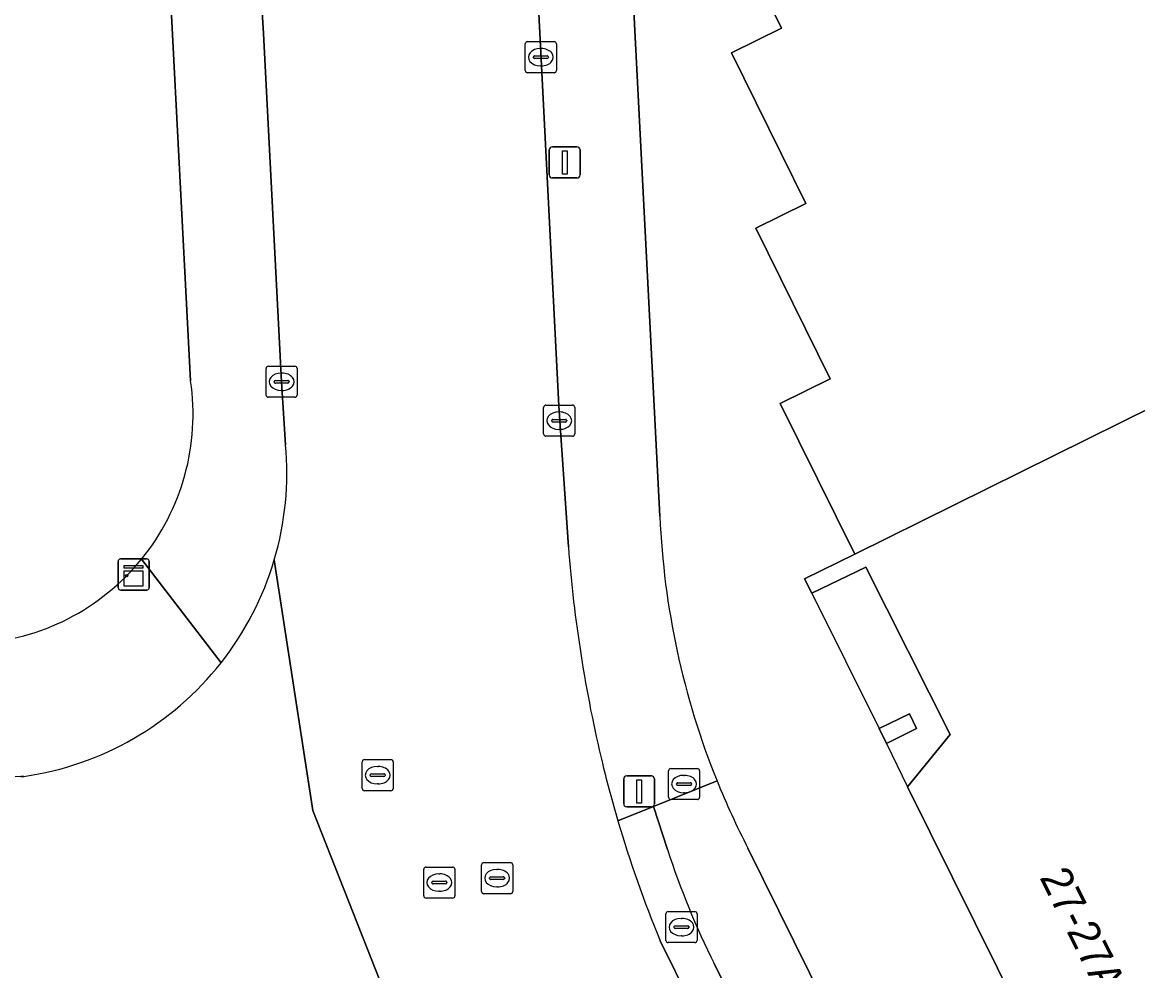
# Model space of a CAD drawing. Extents: x 157692 to 159674, y 381452 to 383291.
# Drawn here: x 158001.47 to 158037.36, y 381590.1 to 381620.62 of the extents above; entities that cross this region are included whole.
import ezdxf

# ---------------------------------------------------------------- set-up
doc = ezdxf.new("R2010")
doc.units = 0
for name, color, linetype in [('IMGEO_Brandkraan', 7, 'Continuous'), ('IMGEO_Erf', 7, 'Continuous'), ('IMGEO_Kast', 7, 'Continuous'), ('IMGEO_Kolk', 7, 'Continuous'), ('IMGEO_Lichtmast', 7, 'Continuous'), ('IMGEO_Pand', 7, 'Continuous'), ('IMGEO_Pand_nummerreeks', 7, 'Continuous'), ('IMGEO_Pand_overbouw', 7, 'Continuous'), ('IMGEO_Rijbaan_lokaal_gesloten', 7, 'Continuous'), ('IMGEO_Rioolput', 7, 'Continuous'), ('IMGEO_Voetpad_open', 7, 'Continuous')]:
    doc.layers.add(name, color=color, linetype=linetype)

msp = doc.modelspace()

# ---------------------------------------------------------------- linework, layer by layer
at = {"layer": 'IMGEO_Brandkraan'}
for p, q in [((158022.261, 381595.679), (158022.261, 381596.531)), ((158022.336, 381596.605), (158023.188, 381596.605)), ((158023.262, 381596.531), (158023.262, 381595.679)), ((158022.52, 381596.099), (158022.52, 381596.111)), ((158022.563, 381596.148), (158022.961, 381596.148)), ((158022.749, 381596.385), (158022.774, 381596.385)), ((158023.004, 381596.111), (158023.004, 381596.099)), ((158022.958, 381596.062), (158022.56, 381596.062)), ((158022.772, 381595.825), (158022.747, 381595.825)), ((158023.188, 381595.605), (158022.336, 381595.605))]:
    msp.add_line(p, q, dxfattribs=at)
for points in [[(158022.261, 381595.679), (158022.261, 381596.531)], [(158022.336, 381596.605), (158023.188, 381596.605)], [(158023.262, 381596.531), (158023.262, 381595.679)], [(158023.188, 381595.605), (158022.336, 381595.605)]]:
    msp.add_lwpolyline(points, dxfattribs=at)
for centre, radius, start, end in [((158022.338, 381596.529), 0.0765, 91.552, 178.448), ((158022.338, 381596.529), 0.0765, 91.552, 178.448), ((158023.186, 381596.529), 0.0765, 1.552, 88.448), ((158023.186, 381596.529), 0.0765, 1.552, 88.448), ((158022.56, 381596.108), 0.0403, 85.8775, 175.7526), ((158022.557, 381596.098), 0.0366, 178.938, 274.7102), ((158022.961, 381596.105), 0.043, 264.8664, 352.4533), ((158022.965, 381596.11), 0.0386, 1.7309, 96.639), ((158022.338, 381595.681), 0.0765, 181.552, 268.448), ((158022.338, 381595.681), 0.0765, 181.552, 268.448), ((158023.186, 381595.681), 0.0765, 271.552, 358.448), ((158023.186, 381595.681), 0.0765, 271.552, 358.448)]:
    msp.add_arc(centre, radius, start, end, dxfattribs=at)
for centre, major_axis, ratio, start_param, end_param in [((158022.748, 381596.105), (-0.387, 0.002), 0.722429, 4.712389, 7.853982), ((158022.773, 381596.105), (-0.39, 0.002), 0.717154, 1.570796, 4.712389)]:
    msp.add_ellipse(centre, major_axis=major_axis, ratio=ratio, start_param=start_param, end_param=end_param, dxfattribs=at)
at = {"layer": 'IMGEO_Erf'}
for points in [[(158006.881, 381609.083), (158005.905, 381627.867), (158005.466, 381636.382), (158005.223, 381641.106), (158032.78, 381654.365), (158038.282, 381657.004), (158060.573, 381667.757), (158067.21, 381670.951), (158069.612, 381672.132), (158075.377, 381674.875), (158095.213, 381684.451), (158107.373, 381690.341), (158121.318, 381697.1), (158122.884, 381701.311), (158109.399, 381729.267), (158106.88, 381734.578), (158102.545, 381743.606), (158102.331, 381744.049), (158099.751, 381749.471), (158099.496, 381750), (158086.302, 381777.417), (158083.311, 381783.632), (158080.659, 381789.142)], [(158024.817, 381594.042), (158031.774, 381579.967), (158034.874, 381573.76), (158035.242, 381573.028), (158037.877, 381567.782), (158119.205, 381608.005), (158123.897, 381610.332), (158120.636, 381617.174), (158120.43, 381617.606), (158147.174, 381630.903), (158223.286, 381668.591), (158222.289, 381671.214), (158214.044, 381692.915)], [(158064.672, 381611.766), (158072.18, 381596.56), (158069.93, 381589.9), (158051.49, 381580.76), (158047.667, 381588.475), (158036.468, 381582.877), (158029.955, 381596.02), (158031.319, 381597.702), (158028.607, 381603.083), (158026.871, 381602.244), (158026.64, 381602.71), (158028.252, 381603.508), (158025.855, 381608.353), (158027.466, 381609.152), (158025.068, 381613.997), (158026.68, 381614.795), (158024.283, 381619.64), (158025.895, 381620.438), (158023.502, 381625.274), (158028.337, 381627.668), (158027.54, 381629.28), (158037.689, 381634.301), (158037.867, 381633.943)], [(158020.806, 381627.665), (158021.984, 381604.726)]]:
    msp.add_lwpolyline(points, dxfattribs=at)
msp.add_lwpolyline([(158030.244, 381597.893), (158029.271, 381597.409), (158029.035, 381597.888), (158030.009, 381598.368)], close=True, dxfattribs=at)
for centre, radius, start, end in [((157999.575, 381608.003), 7.386, 320.8476, 8.406), ((158047.54, 381605.783), 25.578, 182.3676, 201.99), ((157999.568, 381608.009), 7.395, 273.3508, 320.8463), ((158047.696, 381605.866), 25.754, 202.0321, 207.3299)]:
    msp.add_arc(centre, radius, start, end, dxfattribs=at)
at = {"layer": 'IMGEO_Kast'}
for p, q in [((158004.551, 381602.425), (158004.551, 381603.266)), ((158004.551, 381603.266), (158004.551, 381602.425)), ((158004.626, 381603.35), (158005.467, 381603.35)), ((158005.467, 381603.35), (158004.626, 381603.35)), ((158005.551, 381603.275), (158005.551, 381602.434)), ((158005.551, 381602.434), (158005.551, 381603.275)), ((158005.476, 381602.35), (158004.635, 381602.35)), ((158004.635, 381602.35), (158005.476, 381602.35))]:
    msp.add_line(p, q, dxfattribs=at)
for points in [[(158004.746, 381603.14), (158005.346, 381603.14), (158005.346, 381603.055), (158004.746, 381603.055), (158004.746, 381603.14)], [(158004.746, 381602.965), (158005.346, 381602.965), (158005.346, 381602.476), (158004.746, 381602.476), (158004.746, 381602.965)]]:
    msp.add_lwpolyline(points, dxfattribs=at)
msp.add_circle((158004.83, 381602.814), 0.0377, dxfattribs=at)
for centre, start, end in [((158004.629, 381603.272), 92.4484, 184.2845), ((158004.629, 381603.272), 92.4484, 184.2845), ((158005.473, 381603.272), 2.4484, 94.2845), ((158005.473, 381603.272), 2.4484, 94.2845), ((158004.629, 381602.428), 182.4484, 274.2845), ((158004.629, 381602.428), 182.4484, 274.2845), ((158005.473, 381602.428), 272.4484, 4.2845), ((158005.473, 381602.428), 272.4484, 4.2845)]:
    msp.add_arc(centre, 0.0779, start, end, dxfattribs=at)
at = {"layer": 'IMGEO_Kolk'}
for p, q in [((158017.651, 381619.073), (158017.651, 381619.925)), ((158017.726, 381619.999), (158018.578, 381619.999)), ((158018.139, 381619.779), (158018.164, 381619.779)), ((158018.652, 381619.925), (158018.652, 381619.073)), ((158017.91, 381619.493), (158017.91, 381619.505)), ((158018.348, 381619.456), (158017.95, 381619.456)), ((158017.953, 381619.542), (158018.351, 381619.542)), ((158018.394, 381619.505), (158018.394, 381619.493)), ((158018.162, 381619.219), (158018.137, 381619.219)), ((158018.578, 381618.999), (158017.726, 381618.999)), ((158009.31, 381608.626), (158009.31, 381609.478)), ((158009.385, 381609.552), (158010.237, 381609.552)), ((158010.311, 381609.478), (158010.311, 381608.626)), ((158009.569, 381609.046), (158009.569, 381609.058)), ((158010.007, 381609.009), (158009.609, 381609.009)), ((158009.612, 381609.095), (158010.01, 381609.095)), ((158009.798, 381609.332), (158009.823, 381609.332)), ((158010.053, 381609.058), (158010.053, 381609.046)), ((158009.821, 381608.772), (158009.796, 381608.772)), ((158010.237, 381608.552), (158009.385, 381608.552)), ((158018.317, 381608.3), (158019.169, 381608.3)), ((158018.242, 381607.374), (158018.242, 381608.226)), ((158018.73, 381608.08), (158018.755, 381608.08)), ((158019.243, 381608.226), (158019.243, 381607.374)), ((158018.501, 381607.794), (158018.501, 381607.806)), ((158018.939, 381607.757), (158018.541, 381607.757)), ((158018.544, 381607.843), (158018.942, 381607.843)), ((158018.985, 381607.806), (158018.985, 381607.794)), ((158019.169, 381607.3), (158018.317, 381607.3)), ((158018.753, 381607.52), (158018.728, 381607.52)), ((158022.177, 381591.074), (158022.177, 381591.926)), ((158022.252, 381592), (158023.104, 381592)), ((158022.665, 381591.78), (158022.69, 381591.78)), ((158023.178, 381591.926), (158023.178, 381591.074)), ((158022.436, 381591.494), (158022.436, 381591.506)), ((158022.874, 381591.457), (158022.476, 381591.457)), ((158022.479, 381591.543), (158022.877, 381591.543)), ((158022.92, 381591.506), (158022.92, 381591.494)), ((158022.688, 381591.22), (158022.663, 381591.22)), ((158023.104, 381591), (158022.252, 381591))]:
    msp.add_line(p, q, dxfattribs=at)
for points in [[(158017.651, 381619.073), (158017.651, 381619.925)], [(158017.726, 381619.999), (158018.578, 381619.999)], [(158018.652, 381619.925), (158018.652, 381619.073)], [(158018.578, 381618.999), (158017.726, 381618.999)], [(158009.31, 381608.626), (158009.31, 381609.478)], [(158009.385, 381609.552), (158010.237, 381609.552)], [(158010.311, 381609.478), (158010.311, 381608.626)], [(158010.237, 381608.552), (158009.385, 381608.552)], [(158018.317, 381608.3), (158019.169, 381608.3)], [(158018.242, 381607.374), (158018.242, 381608.226)], [(158019.243, 381608.226), (158019.243, 381607.374)], [(158019.169, 381607.3), (158018.317, 381607.3)], [(158022.177, 381591.074), (158022.177, 381591.926)], [(158022.252, 381592), (158023.104, 381592)], [(158023.178, 381591.926), (158023.178, 381591.074)], [(158023.104, 381591), (158022.252, 381591)]]:
    msp.add_lwpolyline(points, dxfattribs=at)
for centre, radius, start, end in [((158017.728, 381619.923), 0.0765, 91.552, 178.448), ((158017.728, 381619.923), 0.0765, 91.552, 178.448), ((158018.576, 381619.923), 0.0765, 1.552, 88.448), ((158018.576, 381619.923), 0.0765, 1.552, 88.448), ((158017.95, 381619.502), 0.0403, 85.8775, 175.7526), ((158017.947, 381619.492), 0.0366, 178.938, 274.7102), ((158018.351, 381619.499), 0.043, 264.8664, 352.4533), ((158018.355, 381619.504), 0.0386, 1.7309, 96.639), ((158017.728, 381619.075), 0.0765, 181.552, 268.448), ((158017.728, 381619.075), 0.0765, 181.552, 268.448), ((158018.576, 381619.075), 0.0765, 271.552, 358.448), ((158018.576, 381619.075), 0.0765, 271.552, 358.448), ((158009.387, 381609.476), 0.0765, 91.552, 178.448), ((158009.387, 381609.476), 0.0765, 91.552, 178.448), ((158010.235, 381609.476), 0.0765, 1.552, 88.448), ((158010.235, 381609.476), 0.0765, 1.552, 88.448), ((158009.609, 381609.055), 0.0403, 85.8775, 175.7526), ((158009.606, 381609.045), 0.0366, 178.938, 274.7102), ((158010.01, 381609.052), 0.043, 264.8664, 352.4533), ((158010.014, 381609.057), 0.0386, 1.7309, 96.639), ((158009.387, 381608.628), 0.0765, 181.552, 268.448), ((158009.387, 381608.628), 0.0765, 181.552, 268.448), ((158010.235, 381608.628), 0.0765, 271.552, 358.448), ((158010.235, 381608.628), 0.0765, 271.552, 358.448), ((158018.319, 381608.224), 0.0765, 91.552, 178.448), ((158018.319, 381608.224), 0.0765, 91.552, 178.448), ((158019.167, 381608.224), 0.0765, 1.552, 88.448), ((158019.167, 381608.224), 0.0765, 1.552, 88.448), ((158018.541, 381607.803), 0.0403, 85.8775, 175.7526), ((158018.538, 381607.793), 0.0366, 178.938, 274.7102), ((158018.942, 381607.8), 0.043, 264.8664, 352.4533), ((158018.946, 381607.805), 0.0386, 1.7309, 96.639), ((158018.319, 381607.376), 0.0765, 181.552, 268.448), ((158018.319, 381607.376), 0.0765, 181.552, 268.448), ((158019.167, 381607.376), 0.0765, 271.552, 358.448), ((158019.167, 381607.376), 0.0765, 271.552, 358.448), ((158022.254, 381591.924), 0.0765, 91.552, 178.448), ((158022.254, 381591.924), 0.0765, 91.552, 178.448), ((158023.102, 381591.924), 0.0765, 1.552, 88.448), ((158023.102, 381591.924), 0.0765, 1.552, 88.448), ((158022.476, 381591.503), 0.0403, 85.8775, 175.7526), ((158022.473, 381591.493), 0.0366, 178.938, 274.7102), ((158022.877, 381591.5), 0.043, 264.8664, 352.4533), ((158022.881, 381591.505), 0.0386, 1.7309, 96.639), ((158022.254, 381591.076), 0.0765, 181.552, 268.448), ((158022.254, 381591.076), 0.0765, 181.552, 268.448), ((158023.102, 381591.076), 0.0765, 271.552, 358.448), ((158023.102, 381591.076), 0.0765, 271.552, 358.448)]:
    msp.add_arc(centre, radius, start, end, dxfattribs=at)
for centre, major_axis, ratio, start_param, end_param in [((158018.138, 381619.499), (-0.387, 0.002), 0.722429, 4.712389, 7.853982), ((158018.163, 381619.499), (-0.39, 0.002), 0.717154, 1.570796, 4.712389), ((158009.797, 381609.052), (-0.387, 0.002), 0.722429, 4.712389, 7.853982), ((158009.822, 381609.052), (-0.39, 0.002), 0.717154, 1.570796, 4.712389), ((158018.729, 381607.8), (-0.387, 0.002), 0.722429, 4.712389, 7.853982), ((158018.754, 381607.8), (-0.39, 0.002), 0.717154, 1.570796, 4.712389), ((158022.664, 381591.5), (-0.387, 0.002), 0.722429, 4.712389, 7.853982), ((158022.689, 381591.5), (-0.39, 0.002), 0.717154, 1.570796, 4.712389)]:
    msp.add_ellipse(centre, major_axis=major_axis, ratio=ratio, start_param=start_param, end_param=end_param, dxfattribs=at)
at = {"layer": 'IMGEO_Lichtmast'}
for p, q in [((158018.525, 381616.613), (158019.315, 381616.613)), ((158019.315, 381616.613), (158018.525, 381616.613)), ((158018.425, 381615.713), (158018.425, 381616.513)), ((158018.425, 381616.513), (158018.425, 381615.713)), ((158019.415, 381616.513), (158019.415, 381615.713)), ((158019.415, 381615.713), (158019.415, 381616.513)), ((158019.315, 381615.613), (158018.525, 381615.613)), ((158018.525, 381615.613), (158019.315, 381615.613)), ((158020.819, 381595.469), (158020.819, 381596.269)), ((158020.819, 381596.269), (158020.819, 381595.469)), ((158020.919, 381596.369), (158021.709, 381596.369)), ((158021.709, 381596.369), (158020.919, 381596.369)), ((158021.809, 381596.269), (158021.809, 381595.469)), ((158021.809, 381595.469), (158021.809, 381596.269)), ((158021.709, 381595.369), (158020.919, 381595.369)), ((158020.919, 381595.369), (158021.709, 381595.369))]:
    msp.add_line(p, q, dxfattribs=at)
for points in [[(158018.845, 381616.488), (158018.995, 381616.488), (158018.995, 381615.738), (158018.845, 381615.738), (158018.845, 381616.488)], [(158021.239, 381596.244), (158021.389, 381596.244), (158021.389, 381595.494), (158021.239, 381595.494), (158021.239, 381596.244)]]:
    msp.add_lwpolyline(points, dxfattribs=at)
for centre, start, end in [((158018.525, 381616.513), 90, 180), ((158018.525, 381616.513), 90, 180), ((158019.315, 381616.513), 0, 90), ((158019.315, 381616.513), 360, 90), ((158018.525, 381615.713), 180, 270), ((158018.525, 381615.713), 180, 270), ((158019.315, 381615.713), 270, 0), ((158019.315, 381615.713), 270, 0), ((158020.919, 381596.269), 90, 180), ((158020.919, 381596.269), 90, 180), ((158021.709, 381596.269), 0, 90), ((158021.709, 381596.269), 360, 90), ((158020.919, 381595.469), 180, 270), ((158020.919, 381595.469), 180, 270), ((158021.709, 381595.469), 270, 0), ((158021.709, 381595.469), 270, 0)]:
    msp.add_arc(centre, 0.1, start, end, dxfattribs=at)
at = {"layer": 'IMGEO_Pand'}
msp.add_lwpolyline([(158037.867, 381633.943), (158037.689, 381634.301), (158027.54, 381629.28), (158028.337, 381627.668), (158023.502, 381625.274), (158025.895, 381620.438), (158024.283, 381619.64), (158026.68, 381614.795), (158025.068, 381613.997), (158027.466, 381609.152), (158025.855, 381608.353), (158028.252, 381603.508), (158037.874, 381608.268), (158041.754, 381600.426), (158064.672, 381611.766), (158053.62, 381634.15), (158047.051, 381630.9)], dxfattribs=at)
for points in [[(158028.252, 381603.508), (158026.64, 381602.71), (158026.871, 381602.244), (158028.607, 381603.083), (158031.319, 381597.702), (158029.955, 381596.02), (158036.468, 381582.877), (158047.667, 381588.475), (158051.49, 381580.76), (158069.93, 381589.9), (158072.18, 381596.56), (158064.672, 381611.766), (158041.754, 381600.426), (158037.874, 381608.268)], [(158029.271, 381597.409), (158030.244, 381597.893), (158030.009, 381598.368), (158029.035, 381597.888)]]:
    msp.add_lwpolyline(points, close=True, dxfattribs=at)
at = {"layer": 'IMGEO_Pand_overbouw'}
msp.add_lwpolyline([(158029.955, 381596.02), (158031.319, 381597.702), (158028.607, 381603.083), (158026.871, 381602.244), (158029.035, 381597.888), (158030.009, 381598.368), (158030.244, 381597.893), (158029.271, 381597.409)], close=True, dxfattribs=at)
at = {"layer": 'IMGEO_Rijbaan_lokaal_gesloten'}
for points in [[(158001.519, 381596.351), (158001.415, 381596.346), (157943.247, 381593.747), (157941.787, 381593.953), (157940.201, 381594.263), (157937.982, 381594.948), (157935.779, 381595.742), (157933.913, 381596.673), (157931.88, 381597.897), (157929.284, 381599.727), (157927.609, 381601.111), (157925.926, 381602.819), (157924.801, 381604.213), (157923.565, 381606.033), (157922.451, 381608.183), (157920.957, 381611.715), (157919.038, 381616.874), (157916.313, 381625.205), (157914.556, 381631.129), (157913.243, 381635.916)], [(158018.776, 381607.631), (158018.733, 381608.273), (158017.739, 381627.652), (158008.979, 381627.772), (158008.948, 381625.733), (158009.154, 381621.489), (158009.233, 381620.257), (158009.812, 381609.052), (158009.936, 381607.028)], [(158019.039, 381603.737), (158018.776, 381607.631)], [(158009.575, 381603.318), (158010.814, 381595.251), (158013.411, 381588.661)], [(158013.411, 381588.661), (158010.814, 381595.251), (158009.575, 381603.318)], [(158017.655, 381585.024), (158019.705, 381580.927), (158025.23, 381569.733), (158025.98, 381568.248), (158031.795, 381571.252), (158031.735, 381571.355), (158030.425, 381574.007), (158021.989, 381591.063)]]:
    msp.add_lwpolyline(points, dxfattribs=at)
for centre, radius, start, end in [((158000.095, 381606.113), 9.884, 343.5729, 5.3118), ((158062.743, 381607.039), 43.828, 184.3208, 193.5424), ((158000.097, 381606.123), 9.884, 321.7748, 343.5141), ((158000.12, 381606.109), 9.857, 278.1593, 321.7576), ((158057.727, 381605.872), 38.679, 193.6015, 196.4423), ((158058.796, 381606.188), 39.793, 196.4431, 202.3392)]:
    msp.add_arc(centre, radius, start, end, dxfattribs=at)
at = {"layer": 'IMGEO_Rioolput'}
for p, q in [((158012.403, 381595.964), (158012.403, 381596.816)), ((158012.478, 381596.89), (158013.33, 381596.89)), ((158013.404, 381596.816), (158013.404, 381595.964)), ((158012.891, 381596.67), (158012.916, 381596.67)), ((158012.662, 381596.384), (158012.662, 381596.396)), ((158013.1, 381596.347), (158012.702, 381596.347)), ((158012.705, 381596.433), (158013.103, 381596.433)), ((158012.914, 381596.11), (158012.889, 381596.11)), ((158013.146, 381596.396), (158013.146, 381596.384)), ((158013.33, 381595.89), (158012.478, 381595.89)), ((158016.32, 381593.576), (158017.172, 381593.576)), ((158014.385, 381592.508), (158014.385, 381593.36)), ((158014.46, 381593.434), (158015.312, 381593.434)), ((158014.873, 381593.214), (158014.898, 381593.214)), ((158015.386, 381593.36), (158015.386, 381592.508)), ((158016.245, 381592.65), (158016.245, 381593.502)), ((158016.733, 381593.356), (158016.758, 381593.356)), ((158017.246, 381593.502), (158017.246, 381592.65)), ((158014.644, 381592.928), (158014.644, 381592.94)), ((158015.082, 381592.891), (158014.684, 381592.891)), ((158014.687, 381592.977), (158015.085, 381592.977)), ((158015.128, 381592.94), (158015.128, 381592.928)), ((158016.504, 381593.07), (158016.504, 381593.082)), ((158016.942, 381593.033), (158016.544, 381593.033)), ((158016.547, 381593.119), (158016.945, 381593.119)), ((158016.988, 381593.082), (158016.988, 381593.07)), ((158014.896, 381592.654), (158014.871, 381592.654)), ((158017.172, 381592.576), (158016.32, 381592.576)), ((158016.756, 381592.796), (158016.731, 381592.796)), ((158015.312, 381592.434), (158014.46, 381592.434))]:
    msp.add_line(p, q, dxfattribs=at)
for points in [[(158012.403, 381595.964), (158012.403, 381596.816)], [(158012.478, 381596.89), (158013.33, 381596.89)], [(158013.404, 381596.816), (158013.404, 381595.964)], [(158013.33, 381595.89), (158012.478, 381595.89)], [(158016.32, 381593.576), (158017.172, 381593.576)], [(158014.385, 381592.508), (158014.385, 381593.36)], [(158014.46, 381593.434), (158015.312, 381593.434)], [(158015.386, 381593.36), (158015.386, 381592.508)], [(158016.245, 381592.65), (158016.245, 381593.502)], [(158017.246, 381593.502), (158017.246, 381592.65)], [(158017.172, 381592.576), (158016.32, 381592.576)], [(158015.312, 381592.434), (158014.46, 381592.434)]]:
    msp.add_lwpolyline(points, dxfattribs=at)
for centre, radius, start, end in [((158012.48, 381596.814), 0.0765, 91.552, 178.448), ((158012.48, 381596.814), 0.0765, 91.552, 178.448), ((158013.328, 381596.814), 0.0765, 1.552, 88.448), ((158013.328, 381596.814), 0.0765, 1.552, 88.448), ((158012.702, 381596.393), 0.0403, 85.8775, 175.7526), ((158012.699, 381596.383), 0.0366, 178.938, 274.7102), ((158013.103, 381596.39), 0.043, 264.8664, 352.4533), ((158013.107, 381596.395), 0.0386, 1.7309, 96.639), ((158012.48, 381595.966), 0.0765, 181.552, 268.448), ((158012.48, 381595.966), 0.0765, 181.552, 268.448), ((158013.328, 381595.966), 0.0765, 271.552, 358.448), ((158013.328, 381595.966), 0.0765, 271.552, 358.448), ((158016.322, 381593.5), 0.0765, 91.552, 178.448), ((158016.322, 381593.5), 0.0765, 91.552, 178.448), ((158017.17, 381593.5), 0.0765, 1.552, 88.448), ((158017.17, 381593.5), 0.0765, 1.552, 88.448), ((158014.462, 381593.358), 0.0765, 91.552, 178.448), ((158014.462, 381593.358), 0.0765, 91.552, 178.448), ((158015.31, 381593.358), 0.0765, 1.552, 88.448), ((158015.31, 381593.358), 0.0765, 1.552, 88.448), ((158014.684, 381592.937), 0.0403, 85.8775, 175.7526), ((158014.681, 381592.927), 0.0366, 178.938, 274.7102), ((158015.085, 381592.934), 0.043, 264.8664, 352.4533), ((158015.089, 381592.939), 0.0386, 1.7309, 96.639), ((158016.544, 381593.079), 0.0403, 85.8775, 175.7526), ((158016.541, 381593.069), 0.0366, 178.938, 274.7102), ((158016.945, 381593.076), 0.043, 264.8664, 352.4533), ((158016.949, 381593.081), 0.0386, 1.7309, 96.639), ((158014.462, 381592.51), 0.0765, 181.552, 268.448), ((158014.462, 381592.51), 0.0765, 181.552, 268.448), ((158015.31, 381592.51), 0.0765, 271.552, 358.448), ((158015.31, 381592.51), 0.0765, 271.552, 358.448), ((158016.322, 381592.652), 0.0765, 181.552, 268.448), ((158016.322, 381592.652), 0.0765, 181.552, 268.448), ((158017.17, 381592.652), 0.0765, 271.552, 358.448), ((158017.17, 381592.652), 0.0765, 271.552, 358.448)]:
    msp.add_arc(centre, radius, start, end, dxfattribs=at)
for centre, major_axis, ratio, start_param, end_param in [((158012.89, 381596.39), (-0.387, 0.002), 0.722429, 4.712389, 7.853982), ((158012.915, 381596.39), (-0.39, 0.002), 0.717154, 1.570796, 4.712389), ((158014.872, 381592.934), (-0.387, 0.002), 0.722429, 4.712389, 7.853982), ((158014.897, 381592.934), (-0.39, 0.002), 0.717154, 1.570796, 4.712389), ((158016.732, 381593.076), (-0.387, 0.002), 0.722429, 4.712389, 7.853982), ((158016.757, 381593.076), (-0.39, 0.002), 0.717154, 1.570796, 4.712389)]:
    msp.add_ellipse(centre, major_axis=major_axis, ratio=ratio, start_param=start_param, end_param=end_param, dxfattribs=at)
at = {"layer": 'IMGEO_Voetpad_open'}
for points in [[(158009.233, 381620.257), (158009.154, 381621.489), (158008.948, 381625.733), (158008.979, 381627.772), (158005.905, 381627.867), (158006.881, 381609.083)], [(158021.984, 381604.726), (158020.806, 381627.665)], [(158017.739, 381627.652), (158018.733, 381608.273), (158018.776, 381607.631), (158019.039, 381603.737)], [(158009.936, 381607.028), (158009.812, 381609.052), (158009.233, 381620.257)], [(158005.302, 381603.34), (158007.862, 381600.007)], [(158007.862, 381600.007), (158005.302, 381603.34)], [(158001.415, 381596.346), (158001.519, 381596.351)], [(158020.63, 381594.924), (158021.777, 381595.384), (158023.823, 381596.205)], [(158023.823, 381596.205), (158021.777, 381595.384), (158022.229, 381593.999)], [(158021.777, 381595.384), (158020.63, 381594.924)], [(158022.229, 381593.999), (158021.777, 381595.384)], [(158023.726, 381590.325), (158032.874, 381571.898), (158035.242, 381573.028), (158034.874, 381573.76), (158031.774, 381579.967), (158024.817, 381594.042)], [(158021.989, 381591.063), (158030.425, 381574.007), (158031.735, 381571.355), (158032.874, 381571.898), (158023.726, 381590.325)]]:
    msp.add_lwpolyline(points, dxfattribs=at)
for centre, radius, start, end in [((157999.575, 381608.003), 7.386, 320.8476, 8.406), ((158000.095, 381606.113), 9.884, 343.5729, 5.3118), ((158047.54, 381605.783), 25.578, 182.3676, 201.99), ((158062.743, 381607.039), 43.828, 184.3208, 193.5424), ((157999.568, 381608.009), 7.395, 273.3508, 320.8463), ((158000.097, 381606.123), 9.884, 321.7748, 343.5141), ((158000.12, 381606.109), 9.857, 278.1593, 321.7576), ((158057.727, 381605.872), 38.679, 193.6015, 196.4423), ((158047.696, 381605.866), 25.754, 202.0321, 207.3299), ((158058.796, 381606.188), 39.793, 196.4431, 202.3392), ((158047.797, 381602.275), 26.874, 197.9358, 206.4018), ((158047.797, 381602.275), 26.874, 197.9358, 206.4018)]:
    msp.add_arc(centre, radius, start, end, dxfattribs=at)

# ---------------------------------------------------------------- texts
at = {"layer": 'IMGEO_Pand_nummerreeks'}
msp.add_text('27-27A', height=1, rotation=296.6354, dxfattribs=at).set_placement((158034.187, 381593.103))

doc.saveas('drawing.dxf')
